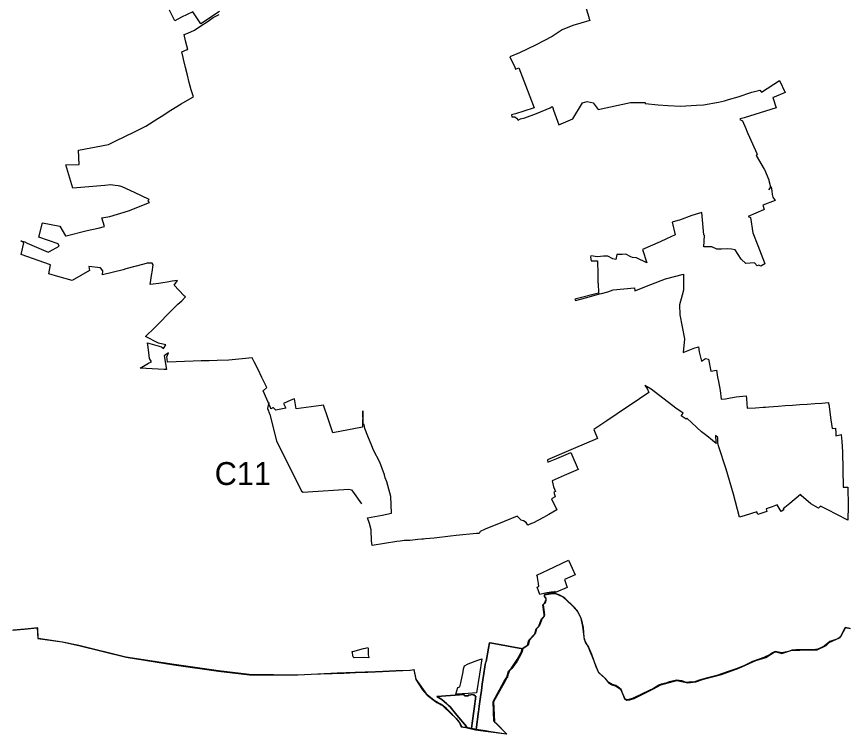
# Model space of a CAD drawing. Extents: x -478490 to -472450, y -1118050 to -1109550.
# Drawn here: x -477155 to -474975, y -1113498 to -1111620 of the extents above; entities that cross this region are included whole.
import ezdxf

# ---------------------------------------------------------------- set-up
doc = ezdxf.new("R2010")
doc.units = 0
for name, color, linetype in [('hranice kú', 7, 'Continuous'), ('Implicitní', 7, 'Continuous'), ('ObPÚ', 7, 'Continuous')]:
    doc.layers.add(name, color=color, linetype=linetype)

msp = doc.modelspace()

# ---------------------------------------------------------------- linework, layer by layer
at = {"layer": 'hranice kú'}
for p, q in [((-475773.3, -1113132.4), (-475752, -1113129.2)), ((-475772.9, -1113137.3), (-475773.3, -1113132.4)), ((-475770, -1113140.3), (-475772.9, -1113137.3)), ((-475752, -1113129.2), (-475745.4, -1113129.5)), ((-475745.4, -1113129.5), (-475736, -1113133)), ((-475736, -1113133), (-475725.4, -1113138.1)), ((-475725.4, -1113138.1), (-475700.6, -1113160.1)), ((-475777.5, -1113158.9), (-475773.1, -1113154.3)), ((-475773.7, -1113184.2), (-475777.5, -1113158.9)), ((-475773.1, -1113154.3), (-475768.7, -1113144)), ((-475768.7, -1113144), (-475770, -1113140.3)), ((-475700.6, -1113160.1), (-475690.7, -1113170.6)), ((-475690.7, -1113170.6), (-475685.4, -1113178)), ((-475685.4, -1113178), (-475676.7, -1113195.1)), ((-475787.5, -1113214.7), (-475780.7, -1113195.1)), ((-475780.7, -1113195.1), (-475774.1, -1113188)), ((-475774.1, -1113188), (-475773.7, -1113184.2)), ((-475676.7, -1113195.1), (-475671.9, -1113217.9)), ((-477165.8, -1113224.6), (-477134.7, -1113222.1)), ((-477134.7, -1113222.1), (-477100.4, -1113219)), ((-477100.4, -1113219), (-477099.3, -1113246.8)), ((-475798.5, -1113234.6), (-475794.6, -1113221.1)), ((-475794.6, -1113221.1), (-475787.5, -1113214.7)), ((-475671.9, -1113217.9), (-475669.7, -1113244.5)), ((-474998.9, -1113244.1), (-474985.7, -1113218)), ((-474985.7, -1113218), (-474972, -1113220.4)), ((-477099.3, -1113246.8), (-477035.2, -1113255.8)), ((-475814.3, -1113251.4), (-475798.5, -1113234.6)), ((-475669.7, -1113244.5), (-475665.3, -1113258.5)), ((-475027.8, -1113257.1), (-474998.9, -1113244.1)), ((-477035.2, -1113255.8), (-476991.4, -1113264.9)), ((-476991.4, -1113264.9), (-476867.7, -1113295.9)), ((-475831.5, -1113273.2), (-475817.6, -1113264.1)), ((-475817.6, -1113264.1), (-475814.3, -1113251.4)), ((-475665.3, -1113258.5), (-475658.2, -1113269.2)), ((-475658.2, -1113269.2), (-475650.2, -1113288)), ((-475059, -1113276.2), (-475035.7, -1113264.8)), ((-475035.7, -1113264.8), (-475027.8, -1113257.1)), ((-475844.9, -1113301.8), (-475835.7, -1113286.1)), ((-475835.7, -1113286.1), (-475833, -1113280.7)), ((-475833, -1113280.7), (-475831.5, -1113273.2)), ((-475650.2, -1113288), (-475638.7, -1113319.8)), ((-475193.7, -1113296.3), (-475171.4, -1113282.5)), ((-475171.4, -1113282.5), (-475166.6, -1113281.7)), ((-475166.6, -1113281.7), (-475151.7, -1113286)), ((-475151.7, -1113286), (-475125.2, -1113277.7)), ((-475125.2, -1113277.7), (-475104.3, -1113277.2)), ((-475104.3, -1113277.2), (-475059, -1113276.2)), ((-476867.7, -1113295.9), (-476743.2, -1113315.4)), ((-475860.6, -1113325.1), (-475844.9, -1113301.8)), ((-475264.7, -1113324.8), (-475219.6, -1113304.2)), ((-475219.6, -1113304.2), (-475193.7, -1113296.3)), ((-476743.2, -1113315.4), (-476626.6, -1113332.5)), ((-476626.6, -1113332.5), (-476544.9, -1113342)), ((-476161.9, -1113331.2), (-476125.1, -1113329.7)), ((-476125.1, -1113329.7), (-476118.9, -1113328.8)), ((-476118.9, -1113328.8), (-476114.9, -1113328.2)), ((-476114.9, -1113328.2), (-476109.7, -1113353.1)), ((-475871.5, -1113348.3), (-475867, -1113332.2)), ((-475867, -1113332.2), (-475860.6, -1113325.1)), ((-475638.7, -1113319.8), (-475631.3, -1113336.1)), ((-475309.3, -1113340.8), (-475264.7, -1113324.8)), ((-476544.9, -1113342), (-476419.1, -1113342)), ((-476419.1, -1113342), (-476383.4, -1113340.4)), ((-476383.4, -1113340.4), (-476335, -1113338.6)), ((-476109.7, -1113353.1), (-476101, -1113365.5)), ((-475878.1, -1113358.5), (-475871.5, -1113348.3)), ((-475631.3, -1113336.1), (-475615.2, -1113350.7)), ((-475615.2, -1113350.7), (-475604.2, -1113363.4)), ((-475468.7, -1113368), (-475426.9, -1113356.4)), ((-475426.9, -1113356.4), (-475397.4, -1113362.5)), ((-475376.6, -1113360.5), (-475357.1, -1113353.3)), ((-475357.1, -1113353.3), (-475309.3, -1113340.8)), ((-476101, -1113365.5), (-476080.1, -1113395.4)), ((-475907.7, -1113411.9), (-475884.7, -1113369.8)), ((-475884.7, -1113369.8), (-475878.1, -1113358.5)), ((-475604.2, -1113363.4), (-475596.5, -1113368.1)), ((-475596.5, -1113368.1), (-475585.2, -1113371.1)), ((-475585.2, -1113371.1), (-475573.8, -1113379.5)), ((-475489.2, -1113379.7), (-475468.7, -1113368)), ((-475397.4, -1113362.5), (-475376.6, -1113360.5)), ((-476080.1, -1113395.4), (-476057.9, -1113411.9)), ((-475573.8, -1113379.5), (-475565.7, -1113398.2)), ((-475565.7, -1113398.2), (-475562.9, -1113404.6)), ((-475538.1, -1113403.7), (-475489.2, -1113379.7)), ((-476057.9, -1113411.9), (-476054.4, -1113413.8)), ((-476054.4, -1113413.8), (-476051.1, -1113415.7)), ((-476051.1, -1113415.7), (-476048.5, -1113417)), ((-476048.5, -1113417), (-476046.4, -1113418.3)), ((-476046.4, -1113418.3), (-476043.5, -1113419.9)), ((-476043.5, -1113419.9), (-476040.8, -1113421.3)), ((-476040.8, -1113421.3), (-476035.4, -1113426.1)), ((-475905.2, -1113463.1), (-475907.7, -1113411.9)), ((-475562.9, -1113404.6), (-475558.3, -1113408.5)), ((-475558.3, -1113408.5), (-475549.6, -1113407.3)), ((-475549.6, -1113407.3), (-475538.1, -1113403.7)), ((-476035.4, -1113426.1), (-476004.1, -1113456)), ((-476004.1, -1113456), (-475996, -1113465.9)), ((-475872.8, -1113496.5), (-475905.2, -1113463.1)), ((-475996, -1113465.9), (-475991.2, -1113477.6)), ((-475991.2, -1113477.6), (-475978.7, -1113479.6)), ((-475978.7, -1113479.6), (-475953.9, -1113485.4)), ((-475953.9, -1113485.4), (-475920.8, -1113490)), ((-475920.8, -1113490), (-475872.8, -1113496.5))]:
    msp.add_line(p, q, dxfattribs=at)
msp.add_lwpolyline([(-476335, -1113338.6), (-476331.3, -1113338.5), (-476328.9, -1113338.5), (-476309.5, -1113337.6), (-476304, -1113337.5), (-476297.9, -1113337.3), (-476282.7, -1113336.7), (-476267.7, -1113335.9), (-476235.2, -1113334.5), (-476196.6, -1113332.7), (-476161.9, -1113331.2)], dxfattribs=at)
at = {"layer": 'Implicitní'}
msp.add_lwpolyline([(-476494.6, -1112629.4), (-476497.8, -1112645), (-476491.9, -1112660.6), (-476474.1, -1112729.8), (-476409.4, -1112861.6), (-476404.5, -1112864.2), (-476392.1, -1112862.7), (-476285.1, -1112856.2), (-476277.9, -1112857.9), (-476271.3, -1112867.9), (-476252.3, -1112894.8)], dxfattribs=at)
at = {"layer": 'ObPÚ'}
for p, q in [((-475744.6, -1113124.7), (-475747, -1113124)), ((-475742.5, -1113125.3), (-475744.6, -1113124.7))]:
    msp.add_line(p, q, dxfattribs=at)
for points in [[(-475667.3, -1111587.5), (-475657.2, -1111621.4), (-475656.6, -1111623.4), (-475654.6, -1111630.4), (-475677.9, -1111636.7), (-475698.4, -1111643.4), (-475726.3, -1111654.9), (-475753.2, -1111671.8), (-475796.4, -1111694.5), (-475838.6, -1111714.6), (-475863.6, -1111725.3), (-475850.8, -1111752.1), (-475848.8, -1111757.6), (-475839.8, -1111754), (-475822.7, -1111798.9), (-475799.8, -1111858.4), (-475826.7, -1111867.4), (-475849.1, -1111873.9), (-475859, -1111876.8), (-475858.5, -1111881.8), (-475850.5, -1111882.4), (-475846, -1111885.5), (-475841.5, -1111890.5), (-475835.8, -1111887.6), (-475824.7, -1111884.4), (-475793.6, -1111873.2), (-475757.8, -1111858.6), (-475752.6, -1111855.2), (-475751.9, -1111856.2), (-475751.3, -1111858.9), (-475749.1, -1111864.3), (-475735.2, -1111903), (-475699, -1111887), (-475673.7, -1111845.3), (-475661.5, -1111842.2), (-475645.4, -1111845.7), (-475632.5, -1111862.8), (-475547.6, -1111845), (-475509.3, -1111844.8), (-475509.4, -1111846.9), (-475475.1, -1111850.7), (-475449.8, -1111852.2), (-475416.4, -1111853.9), (-475403.4, -1111853.3), (-475374.7, -1111851.3), (-475356.5, -1111850.4), (-475317.7, -1111843.9), (-475302.2, -1111839.9), (-475298.9, -1111839.2), (-475291.5, -1111836.7), (-475266.1, -1111830), (-475230.2, -1111817.8), (-475212.6, -1111813.1), (-475209, -1111812.4), (-475205, -1111817.9), (-475157.9, -1111786.7), (-475143.1, -1111818.7), (-475171.7, -1111830.3), (-475175.1, -1111831.6), (-475166.6, -1111858.8), (-475250, -1111885.1), (-475260.4, -1111887.5), (-475261.4, -1111889.2), (-475254.8, -1111892.9), (-475246.3, -1111913), (-475243.5, -1111919.3), (-475240.6, -1111926), (-475236.6, -1111935), (-475217.4, -1111978.1), (-475216.4, -1111980.6), (-475219.2, -1111983.5), (-475197.7, -1112019.3), (-475197.5, -1112020.1), (-475186.2, -1112046.7), (-475185.4, -1112048.9), (-475181.2, -1112065.4), (-475185.4, -1112073.3), (-475179.8, -1112065.2), (-475178.2, -1112076.8), (-475177.1, -1112085), (-475175.1, -1112092.7)], [(-476624, -1111606.8), (-476672.6, -1111638.9), (-476693.6, -1111607.2), (-476722.7, -1111621.8), (-476740.9, -1111630.8), (-476754.6, -1111602.9)], [(-476716.8, -1112349.4), (-476742.1, -1112322.2), (-476733.5, -1112310), (-476747.3, -1112312.3), (-476761, -1112314.4), (-476772.2, -1112316.4), (-476782.1, -1112317.8), (-476805.1, -1112321.1), (-476800.4, -1112292.3), (-476799.8, -1112288.9), (-476796.8, -1112269.7), (-476799.8, -1112265.1), (-476813.2, -1112264.9), (-476821.5, -1112267.2), (-476869, -1112280.1), (-476875.9, -1112282), (-476929.6, -1112295.7), (-476928.6, -1112284.7), (-476935.1, -1112277.1), (-476965.2, -1112273.8), (-476964.1, -1112283.8), (-477009.1, -1112309.9), (-477046.3, -1112299.5), (-477070.7, -1112293.1), (-477066, -1112269.4), (-477142.6, -1112241.9), (-477135.3, -1112211.7), (-477143.2, -1112206.4), (-477133.2, -1112209.5), (-477127, -1112212.2), (-477072, -1112236.3), (-477068.2, -1112234.2), (-477043, -1112220.5), (-477046.2, -1112214.4), (-477096.2, -1112196.9), (-477087, -1112159.4), (-477041.6, -1112167.7), (-477027.1, -1112193.6), (-477024.7, -1112193), (-476969.7, -1112179.8), (-476941.5, -1112173.1), (-476924.9, -1112169.2), (-476932, -1112146), (-476910.3, -1112142.8), (-476862, -1112127.9), (-476806.8, -1112106.1), (-476811.6, -1112102), (-476807.6, -1112098), (-476845.7, -1112080.1), (-476878, -1112065), (-476883.2, -1112063.6), (-476885.7, -1112063.1), (-476889.1, -1112062.6), (-476896.8, -1112061.7), (-476908.9, -1112060.2), (-476924.1, -1112061.6), (-477007.9, -1112069), (-477025.9, -1112007.4), (-476990.5, -1112007), (-476992.4, -1111969.7), (-476913.9, -1111954.4), (-476895, -1111945), (-476846.1, -1111921.6), (-476816.5, -1111906.9), (-476785, -1111886.7), (-476776.6, -1111881.3), (-476750.7, -1111864.8), (-476724.3, -1111848.2), (-476695, -1111831.9), (-476691.4, -1111829.9), (-476697.9, -1111811.9), (-476703.4, -1111792.7), (-476707.7, -1111773.2), (-476712.7, -1111753.4), (-476717.9, -1111731.2), (-476718.9, -1111726.7), (-476722.5, -1111711.7), (-476708, -1111706.3), (-476706.6, -1111705.8), (-476709.3, -1111696.3), (-476712.4, -1111683.4), (-476716.3, -1111667), (-476706.5, -1111662.8), (-476689.2, -1111655), (-476672.4, -1111644.1), (-476656.2, -1111633.3), (-476639.8, -1111622.5), (-476624.6, -1111614.3)], [(-475175.1, -1112092.7), (-475169.4, -1112100.7), (-475201.2, -1112112.9), (-475197.7, -1112124.4), (-475199.7, -1112125.2), (-475239.7, -1112142.5), (-475233.8, -1112145.8), (-475227.7, -1112185.9), (-475214.4, -1112218.3), (-475197.3, -1112264.1), (-475196.2, -1112266.6), (-475206.7, -1112272.6), (-475211.8, -1112270.3), (-475216.6, -1112272.3), (-475223.2, -1112264.3), (-475246.3, -1112265.9), (-475258.3, -1112254.1), (-475273.6, -1112230.2), (-475283.6, -1112228.6), (-475293.4, -1112227.1), (-475310, -1112228.3), (-475321.7, -1112228), (-475335.4, -1112221.9), (-475355.5, -1112221.9), (-475353.9, -1112192.4), (-475355.8, -1112190.7), (-475361.4, -1112132.7), (-475386.9, -1112139.9), (-475419.2, -1112152.4), (-475423.8, -1112153.6), (-475439, -1112157.5), (-475430.9, -1112190.6), (-475453.5, -1112201.6), (-475470.5, -1112209.5), (-475516.3, -1112229.6), (-475504.9, -1112263.8), (-475531.9, -1112251.3), (-475542.4, -1112249.8), (-475547.1, -1112248.7), (-475559.9, -1112241.8), (-475569.8, -1112242.1), (-475583.6, -1112242.6), (-475586.4, -1112255.5), (-475593.7, -1112253.8), (-475606.8, -1112246.9), (-475618.2, -1112246.2), (-475633.8, -1112248.7), (-475652, -1112245.7), (-475652.2, -1112249.6), (-475650.9, -1112258.7), (-475634, -1112258.7), (-475633.3, -1112294.1), (-475633, -1112316.4), (-475632.9, -1112317.5), (-475631.8, -1112343.6), (-475693.2, -1112358.8), (-475692.2, -1112362.7), (-475661.8, -1112354.6), (-475628.7, -1112345.5), (-475623.9, -1112344.2), (-475607, -1112340), (-475592.9, -1112335.1), (-475565.4, -1112331.9), (-475537.3, -1112329.1), (-475536.7, -1112337.2), (-475494.7, -1112320.7), (-475456.5, -1112305.8), (-475409.4, -1112293.6), (-475409.3, -1112335.9), (-475412.3, -1112349), (-475419.4, -1112373.5), (-475419, -1112399.7), (-475406.5, -1112462.9), (-475410.2, -1112498.6), (-475379.2, -1112486.8), (-475372.2, -1112484.3), (-475370, -1112483.5), (-475368.5, -1112496.7), (-475361.8, -1112521.1), (-475351.9, -1112514.1), (-475343.5, -1112516.4), (-475337.6, -1112547.5), (-475322.6, -1112544.6), (-475319.8, -1112562.9), (-475317.8, -1112574.1), (-475313.4, -1112597.9), (-475310.2, -1112621.1), (-475299.6, -1112619.4), (-475286, -1112617.2), (-475271, -1112614.7), (-475244.9, -1112612.1), (-475244.2, -1112620), (-475242.4, -1112644.2), (-475220.3, -1112643.3), (-475200.7, -1112641.8), (-475194.4, -1112641.2)], [(-475821.3, -1112943.2), (-475827.5, -1112939.1), (-475834.2, -1112937.6), (-475844.4, -1112927.1), (-475878.8, -1112941), (-475928, -1112960.8), (-475929.8, -1112961.5), (-475941.2, -1112967.3), (-475944, -1112972.5), (-475951.3, -1112972.4), (-476004.5, -1112977.3), (-476018.9, -1112979.2), (-476061.7, -1112984), (-476084.3, -1112986.2), (-476089.5, -1112986.6), (-476094, -1112987), (-476104.8, -1112988), (-476125.8, -1112990), (-476140.4, -1112990.8), (-476151, -1112991.9), (-476159.5, -1112992.8), (-476224.1, -1113003.1), (-476225.4, -1112991.1), (-476226.7, -1112962.3), (-476231.3, -1112946.2), (-476236.3, -1112930.9), (-476197.9, -1112923.9), (-476173.1, -1112918.5), (-476175.1, -1112875.5), (-476185.9, -1112836.7), (-476189.6, -1112826.3), (-476192, -1112818.9), (-476203.9, -1112785.9), (-476220.3, -1112754.1), (-476224.8, -1112742.7), (-476235.1, -1112717.1), (-476243.4, -1112697.3), (-476244.9, -1112686.6), (-476247.7, -1112687.1), (-476248.8, -1112651.6), (-476249, -1112693.6), (-476326.6, -1112708.5), (-476339.7, -1112669.9), (-476351, -1112636.6), (-476357.4, -1112637.7), (-476422.9, -1112645.9), (-476427.4, -1112619.4), (-476430.3, -1112620.4), (-476436.9, -1112623.5), (-476455.7, -1112631.7), (-476450.1, -1112644), (-476476, -1112649.4), (-476482.1, -1112643.1), (-476483.7, -1112643.8), (-476488.8, -1112645.9), (-476490.1, -1112642.9), (-476509, -1112598.8), (-476499.6, -1112590.5), (-476512.7, -1112563.7), (-476522.7, -1112543.4), (-476532.6, -1112523.3), (-476537.9, -1112512.5), (-476599.3, -1112518.8), (-476629.5, -1112519.4), (-476650.7, -1112520.2), (-476671.7, -1112520.8), (-476692.9, -1112521.6), (-476759.4, -1112524), (-476760.7, -1112514.9), (-476761.7, -1112509.6), (-476757.2, -1112499.1), (-476768.7, -1112507.4), (-476762, -1112543), (-476768.7, -1112542.8), (-476830.9, -1112539.2), (-476809.4, -1112526.4), (-476801.8, -1112522.8), (-476806.4, -1112514.5), (-476810.3, -1112484.8), (-476811.8, -1112473.6), (-476775.7, -1112483.8), (-476770.1, -1112487.8), (-476764, -1112478.9), (-476783.5, -1112474.4), (-476817.6, -1112456.8), (-476793.5, -1112434), (-476780, -1112420.5), (-476777, -1112417.7), (-476761.2, -1112401.3), (-476751.7, -1112391.3), (-476745.1, -1112384.2), (-476732.8, -1112372.5), (-476722.4, -1112363.2), (-476712.3, -1112353.3), (-476715.3, -1112351), (-476716.8, -1112349.4)], [(-475194.4, -1112641.2), (-475185.4, -1112640.5), (-475161.7, -1112639.1), (-475142.9, -1112637.6), (-475124, -1112636.4), (-475105, -1112635), (-475085.7, -1112634.1), (-475065.1, -1112632.4), (-475047.4, -1112630.9), (-475030, -1112629.5), (-475029.4, -1112633.9), (-475028.6, -1112633.9), (-475023.8, -1112674.9), (-475019.8, -1112697.4), (-475011, -1112696.8), (-475010.4, -1112709.6), (-475010.4, -1112716.5), (-474996.6, -1112713), (-474996.4, -1112714.1), (-474994.6, -1112731.6), (-474993.4, -1112758.1), (-474991.2, -1112850.8), (-474978.9, -1112851.1), (-474978.1, -1112899.4), (-474979.1, -1112937.4), (-475032.7, -1112909.2), (-475050.7, -1112900.4), (-475056.1, -1112905.6), (-475076, -1112894.2), (-475100.9, -1112872.7), (-475103.2, -1112870.5), (-475130.9, -1112893.6), (-475148.6, -1112907.7), (-475146.9, -1112909.8), (-475153.2, -1112914.5), (-475161.6, -1112901.4), (-475164.2, -1112897), (-475176.8, -1112902.4), (-475190.4, -1112906.6), (-475193, -1112907.4), (-475191.2, -1112914.5), (-475215, -1112922.7), (-475216.2, -1112918.1), (-475216.8, -1112915.6), (-475247.6, -1112925.1), (-475262.7, -1112929.7), (-475267.7, -1112909.4), (-475278.3, -1112869.6), (-475297.5, -1112803.4), (-475317.6, -1112742.9), (-475319.3, -1112735), (-475319.6, -1112720.8), (-475325.4, -1112715.5), (-475324.9, -1112732.2), (-475323.6, -1112736.3), (-475347.7, -1112717), (-475362, -1112705.8), (-475387.6, -1112682.8), (-475400.2, -1112670.4), (-475402.3, -1112672.8), (-475415.1, -1112664), (-475409.9, -1112657), (-475429, -1112644), (-475493.6, -1112594.9), (-475510, -1112585), (-475504.4, -1112592.7), (-475500.2, -1112602.9), (-475548.7, -1112636.1), (-475563.2, -1112645.9), (-475582.4, -1112659), (-475609.9, -1112677.6), (-475644, -1112700.2), (-475634.1, -1112723.5), (-475698.2, -1112750.9), (-475765.5, -1112779.2), (-475764.2, -1112785.3), (-475762.8, -1112784.7), (-475740.8, -1112775.6), (-475704.4, -1112759.9), (-475684.8, -1112805), (-475721.1, -1112820.7), (-475752.9, -1112834.2), (-475749.2, -1112850), (-475744.5, -1112862.5), (-475748.9, -1112864.2), (-475744.9, -1112876.6), (-475754.6, -1112881.6), (-475740.7, -1112910.4), (-475761.5, -1112922.4), (-475769.3, -1112926.9), (-475775.6, -1112930.1), (-475776.9, -1112931.4), (-475801.9, -1112943.8), (-475807.1, -1112946.1), (-475816.2, -1112950.3), (-475821.3, -1112943.2)], [(-475710, -1113041.8), (-475709.1, -1113043.6), (-475700.1, -1113063.1), (-475692.4, -1113080.1), (-475720.3, -1113092.4), (-475713.9, -1113113), (-475742.3, -1113125.9), (-475744.3, -1113125.4), (-475747.1, -1113125.2), (-475755.1, -1113125.3), (-475766.7, -1113127.6), (-475774.9, -1113128.9), (-475785.3, -1113131.9), (-475792, -1113112.6), (-475790.1, -1113112), (-475787.6, -1113111.1), (-475788.9, -1113103), (-475791.1, -1113087.2), (-475791.6, -1113085.8), (-475792.8, -1113082.4), (-475793.3, -1113080.9), (-475763.7, -1113066.8), (-475710, -1113041.8)], [(-475198.5, -1113296.9), (-475213.9, -1113301.5), (-475228.9, -1113307.4), (-475249.6, -1113317.1), (-475268.9, -1113325.3), (-475289.9, -1113332.2), (-475322.2, -1113343.7), (-475349.4, -1113350.5), (-475368.4, -1113355.9), (-475377.8, -1113359.3), (-475383.5, -1113360.7), (-475389.5, -1113360.4), (-475400.9, -1113361.8), (-475413.6, -1113357.9), (-475426.3, -1113355.6), (-475446.3, -1113360.1), (-475455.6, -1113363.4), (-475467.2, -1113366.3), (-475474.1, -1113369.3), (-475488, -1113377.9), (-475515.5, -1113390.5), (-475540.5, -1113402.8), (-475554.8, -1113406.9), (-475558.9, -1113406.6), (-475561.4, -1113405.6), (-475563.8, -1113403.3), (-475572.2, -1113380.4), (-475580.7, -1113372.9), (-475585.9, -1113369.9), (-475595.6, -1113367.1), (-475604.5, -1113362.3), (-475615.8, -1113350), (-475631.3, -1113334.8), (-475635.3, -1113326.5), (-475648.5, -1113293.4), (-475653.1, -1113280.5), (-475657.3, -1113271.2), (-475665.2, -1113257.3), (-475668.2, -1113249.8), (-475669.4, -1113243.4), (-475672.3, -1113215.6), (-475676.7, -1113194.5), (-475681.4, -1113184.9), (-475687.6, -1113173.9), (-475695.2, -1113164.7), (-475720.1, -1113141.3), (-475725.2, -1113137.8), (-475733.2, -1113133.4), (-475747.2, -1113128.6), (-475754.8, -1113128.7), (-475760.6, -1113129.4), (-475770.6, -1113131.7), (-475773.2, -1113131.8), (-475773.5, -1113135), (-475772.5, -1113137.4), (-475769.1, -1113140.7), (-475769.1, -1113142.3), (-475769.2, -1113146.8), (-475770, -1113152.1), (-475772.1, -1113154.5), (-475776.3, -1113158.9), (-475773, -1113185.1), (-475773.4, -1113188.3), (-475779.3, -1113194.7), (-475783.8, -1113205.7), (-475786.5, -1113214.6), (-475794, -1113221.4), (-475797.1, -1113234.2), (-475812.5, -1113251.2), (-475815.7, -1113264.3), (-475829.4, -1113273.5), (-475914.9, -1113258.4), (-475916.9, -1113258.2), (-475919.5, -1113272.1), (-475925.9, -1113307.1), (-475927.6, -1113310.8), (-475929.4, -1113321.1), (-475931.8, -1113338.7), (-475934.6, -1113354.7), (-475936.1, -1113366.1), (-475938.2, -1113382.8), (-475940.3, -1113399.7), (-475943.8, -1113423.9), (-475945, -1113432.9), (-475945.9, -1113437.9), (-475951.7, -1113485.1), (-475955.2, -1113484.4), (-475964.2, -1113482.6), (-475962, -1113468.4), (-475956.7, -1113430.6), (-475952.3, -1113398), (-475954.6, -1113398.1), (-475955, -1113394.8), (-475956.8, -1113395), (-475958.7, -1113395.2), (-475958.8, -1113393.6)], [(-475958.8, -1113393.6), (-475972.4, -1113394.8), (-475972.3, -1113396.4), (-475982.5, -1113397.2), (-475982.8, -1113392.9), (-476055, -1113398.4), (-476042.1, -1113406.1), (-476028.8, -1113417.9), (-476025.5, -1113420.8), (-476019.5, -1113425.8), (-476002, -1113447), (-475977.1, -1113476.9), (-475976.7, -1113480), (-475983.3, -1113479.3), (-475989, -1113477.7), (-475994, -1113468.3), (-475999.4, -1113460.9), (-476018.3, -1113441), (-476029.3, -1113430.2), (-476038, -1113422.8), (-476044.7, -1113418.6), (-476051.6, -1113415.3), (-476061.6, -1113408.9), (-476079.9, -1113394.1), (-476091, -1113380.9), (-476108.8, -1113353.8), (-476114, -1113328.4), (-476124.3, -1113330.1), (-476161, -1113331.2), (-476195.9, -1113333.1), (-476234.3, -1113334.6), (-476239.3, -1113334.9), (-476242.1, -1113335), (-476268.1, -1113336.1), (-476315.8, -1113337.8), (-476383.3, -1113341), (-476418.4, -1113342.7), (-476545.7, -1113341.3), (-476626.5, -1113331.7), (-476742.5, -1113314.7), (-476868.4, -1113295.6), (-476991.4, -1113264.8), (-477034.1, -1113256), (-477098.3, -1113246.9), (-477099.1, -1113218.9), (-477133.3, -1113222.8), (-477164, -1113225.1)], [(-474973.5, -1113220.4), (-474985.4, -1113217.8), (-474998.6, -1113242.1), (-475005.2, -1113247.5), (-475026, -1113254.6), (-475041.2, -1113266.8), (-475046.5, -1113269.7), (-475059.7, -1113275.4), (-475063.6, -1113275.2), (-475074, -1113276.3), (-475114.8, -1113276.6), (-475125.6, -1113277.5), (-475134.1, -1113280.6), (-475152.1, -1113284.6), (-475168.9, -1113281), (-475176.6, -1113284.4), (-475182.5, -1113288.4), (-475198.5, -1113296.9)], [(-475919.5, -1113272.1), (-475916.9, -1113258.2), (-475914.9, -1113258.4), (-475829.4, -1113273.5), (-475831.9, -1113283.6), (-475833.9, -1113286.9), (-475844.8, -1113306.3), (-475858.4, -1113325.5), (-475865.5, -1113332.6), (-475866.6, -1113337), (-475868.6, -1113341.6), (-475870.1, -1113348.5), (-475871.2, -1113349.7), (-475876.2, -1113358.8), (-475882.6, -1113370.2), (-475902.5, -1113404.8), (-475906.8, -1113412.2), (-475905.7, -1113429.1), (-475903.9, -1113464.4), (-475898.5, -1113469.1), (-475871.7, -1113497.5), (-475884.8, -1113495.4), (-475919, -1113489.8), (-475927.3, -1113488.7), (-475951.7, -1113485.1), (-475945.9, -1113437.9), (-475945, -1113432.9), (-475943.8, -1113423.9), (-475940.3, -1113399.7), (-475938.2, -1113382.8), (-475936.1, -1113366.1), (-475934.6, -1113354.7), (-475931.8, -1113338.7), (-475929.4, -1113321.1), (-475927.6, -1113310.8), (-475925.9, -1113307.1), (-475919.5, -1113272.1)], [(-476235, -1113270.3), (-476234.9, -1113272.9), (-476234.7, -1113278.9), (-476234.1, -1113289.1), (-476233, -1113296.2), (-476232.8, -1113297.4), (-476246.2, -1113296.9), (-476271, -1113297.1), (-476274, -1113294.7), (-476276.7, -1113280.9), (-476275, -1113280.4), (-476246.5, -1113273.2), (-476241.6, -1113271.9), (-476235, -1113270.3)], [(-475937.1, -1113300.3), (-475943.5, -1113340.5), (-475950.6, -1113389.2), (-475972.8, -1113390.3), (-476004.6, -1113392.3), (-475999.6, -1113375.3), (-475994.2, -1113373.4), (-475992.2, -1113363.2), (-475986.2, -1113334.1), (-475984.9, -1113325.8), (-475982, -1113318.2), (-475972.8, -1113313.2), (-475947.2, -1113303.8), (-475937.1, -1113300.3)], [(-476055, -1113398.4), (-475982.8, -1113392.9), (-475982.5, -1113397.2), (-475972.3, -1113396.4), (-475972.4, -1113394.8), (-475958.8, -1113393.6), (-475958.7, -1113395.2), (-475956.8, -1113395), (-475955, -1113394.8), (-475954.6, -1113398.1), (-475952.3, -1113398), (-475956.7, -1113430.6), (-475962, -1113468.4), (-475964.2, -1113482.6), (-475976.7, -1113480), (-475977.1, -1113476.9), (-476002, -1113447), (-476019.5, -1113425.8), (-476025.5, -1113420.8), (-476028.8, -1113417.9), (-476042.1, -1113406.1), (-476055, -1113398.4)]]:
    msp.add_lwpolyline(points, dxfattribs=at)

# ---------------------------------------------------------------- texts
at = {"layer": 'Implicitní'}
msp.add_text('C11', height=60, dxfattribs=at).set_placement((-476636.1, -1112845.3))

doc.saveas('drawing.dxf')
